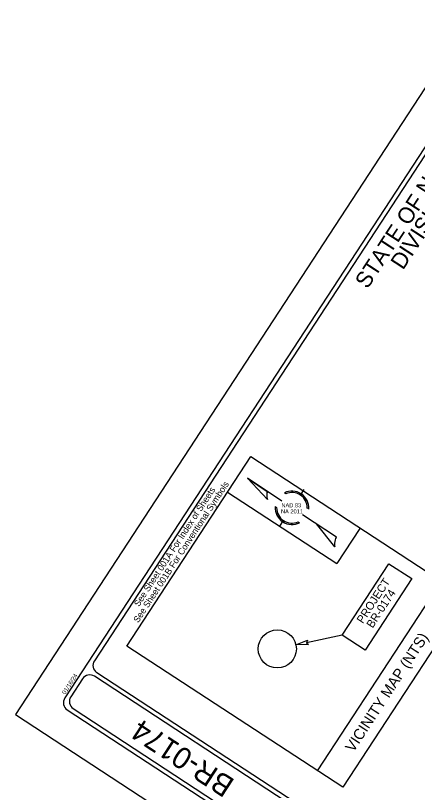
# Model space of a CAD drawing. Extents: x 1190029 to 2382315, y 163128 to 334830.
# Drawn here: x 2378613 to 2379548, y 331527 to 333329 of the extents above; entities that cross this region are included whole.
import ezdxf

# ---------------------------------------------------------------- set-up
doc = ezdxf.new("R2010")
doc.units = 0
for name, color, linetype in [('Exist Property Corner CELL', 7, 'Continuous'), ('Exist Utilities Telephone UG FO SUE LOS B Text', 7, 'Continuous'), ('P_NCDOT_Vertical_Profile_Strip_Grade', 7, 'Continuous'), ('Scratch_Level_4', 7, 'Continuous'), ('Sheet Block Title CELL', 7, 'Continuous'), ('Sheet PE Seal CELL', 7, 'Continuous'), ('z - Construction', 7, 'Continuous')]:
    doc.layers.add(name, color=color, linetype=linetype)

msp = doc.modelspace()

# ---------------------------------------------------------------- linework, layer by layer
at = {"layer": 'Exist Property Corner CELL'}
msp.add_line((2379261.2, 332185.5), (2379261.2, 332185.5), dxfattribs=at)
msp.add_line((2379261.2, 332185.5), (2379261.2, 332185.5), dxfattribs=at)
msp.add_line((2379261.2, 332185.5), (2379261.2, 332185.5), dxfattribs=at)
msp.add_line((2379261.2, 332185.5), (2379261.2, 332185.5), dxfattribs=at)
msp.add_line((2379261.2, 332185.5), (2379261.2, 332185.5), dxfattribs=at)
msp.add_line((2379261.2, 332185.5), (2379261.2, 332185.5), dxfattribs=at)
msp.add_line((2379261.2, 332185.5), (2379261.2, 332185.5), dxfattribs=at)
msp.add_line((2379261.2, 332185.5), (2379261.2, 332185.5), dxfattribs=at)
msp.add_line((2379261.2, 332185.5), (2379261.2, 332185.5), dxfattribs=at)
msp.add_line((2379261.2, 332185.5), (2379261.2, 332185.5), dxfattribs=at)
msp.add_line((2379261.2, 332185.5), (2379261.2, 332185.5), dxfattribs=at)
for start_param, end_param in [(0.216388, 2.908219), (0.201328, 3.141593)]:
    msp.add_ellipse((2379261.2, 332185.5), major_axis=(0.000000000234, 0.000000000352), ratio=0.461098, start_param=start_param, end_param=end_param, dxfattribs=at)
at = {"layer": 'Exist Utilities Telephone UG FO SUE LOS B Text'}
for p, q in [((2380483.9, 334428.7), (2378727.4, 331741.9)), ((2380486.9, 334414.8), (2378796.1, 331828.5)), ((2378871.7, 331862.7), (2379159.9, 332303.6)), ((2379159.9, 332303.6), (2379662.2, 331975.2)), ((2379105.8, 332220.7), (2379360.2, 332054.4)), ((2379413.9, 332136.4), (2379360.2, 332054.4)), ((2379602.6, 332013.1), (2379314.3, 331572.2)), ((2379662.2, 331975.2), (2379374, 331534.3)), ((2379374, 331534.3), (2378871.7, 331862.7)), ((2380462, 330703.5), (2378796.4, 331792.4)), ((2380157.8, 330914.3), (2378801.9, 331800.8)), ((2378747.1, 331717.1), (2380412.8, 330628.2)), ((2378733.2, 331714.3), (2380415.6, 330614.4))]:
    msp.add_line(p, q, dxfattribs=at)
msp.add_lwpolyline([(2378768.6, 331786.7), (2378741.3, 331744.8)], dxfattribs=at)
for centre, start, end in [((2378812.8, 331817.5), 146.8248, 236.8248), ((2378785.4, 331775.7), 56.8248, 146.8248), ((2378744.1, 331731), 146.8248, 236.8248), ((2378758, 331733.9), 146.8248, 236.8248)]:
    msp.add_arc(centre, 20, start, end, dxfattribs=at)
at = {"layer": 'P_NCDOT_Vertical_Profile_Strip_Grade'}
for p, q in [((2379199, 332203.8), (2379152.1, 332252.9)), ((2379232.5, 332199.7), (2379152.2, 332252.9)), ((2379152.2, 332252.9), (2379200.5, 332220.9)), ((2379200.5, 332220.9), (2379199.1, 332221.8)), ((2379199.1, 332221.8), (2379199.1, 332221.8)), ((2379275.5, 332214), (2379284.2, 332227)), ((2379241.4, 332216.9), (2379238.1, 332219)), ((2379275.5, 332214), (2379277.3, 332216.7)), ((2379277.3, 332216.7), (2379275.5, 332214)), ((2379216.8, 332187.1), (2379216.9, 332187)), ((2379216.9, 332187), (2379220.1, 332184.9)), ((2379359.4, 332115.6), (2379280.2, 332168)), ((2379294.7, 332181.5), (2379291.4, 332183.7)), ((2379294.7, 332181.5), (2379294.7, 332181.5)), ((2379227.4, 332141.4), (2379236.1, 332154.5)), ((2379236.1, 332154.5), (2379234.2, 332151.7)), ((2379234.2, 332151.7), (2379236.1, 332154.5)), ((2379270.3, 332151.7), (2379273.5, 332149.5)), ((2379311.8, 332147.1), (2379355.1, 332093.8)), ((2379359.4, 332115.6), (2379311.8, 332147.1))]:
    msp.add_line(p, q, dxfattribs=at)
for radius, start, end in [(39, 355.9746, 116.9338), (39, 56.4542, 116.9338), (35.7, 359.0548, 113.8536), (35.7, 56.4542, 113.8536), (39, 175.8884, 297.0201), (35.7, 178.9574, 293.9511), (39, 236.4542, 297.0201), (35.7, 236.4542, 293.9511)]:
    msp.add_arc((2379255.8, 332184.2), radius, start, end, dxfattribs=at)
for centre, major_axis, ratio, start_param, end_param in [((2379199.6, 332212.3), (-0.65, 9.54), 0.261723, 6.225794, 8.917625), ((2379255.8, 332184.2), (-29.8, 19.7), 0.998737, 3.71058, 4.712389), ((2379255.8, 332184.2), (-32.5, 21.6), 0.998737, 3.657116, 4.712389), ((2379255.8, 332184.2), (-32.5, 21.6), 0.998737, 0.514018, 1.570796), ((2379255.8, 332184.2), (-29.8, 19.7), 0.998737, 0.567287, 1.570796), ((2379357.5, 332104.5), (1.8, 11.1), 0.225493, 6.280036, 9.220301)]:
    msp.add_ellipse(centre, major_axis=major_axis, ratio=ratio, start_param=start_param, end_param=end_param, dxfattribs=at)
at = {"layer": 'Scratch_Level_4'}
msp.add_line((2379372.6, 331887.9), (2379289.8, 331870.4), dxfattribs=at)
msp.add_circle((2379221.7, 331856.1), 44.3, dxfattribs=at)
at = {"layer": 'Sheet Block Title CELL'}
msp.add_lwpolyline([(2379294.2, 331866.4), (2379265, 331865.2), (2379292.2, 331876.2), (2379289.7, 331870.5)], close=True, dxfattribs=at)
at = {"layer": 'Sheet PE Seal CELL'}
msp.add_lwpolyline([(2379372.6, 331887.9), (2379481.4, 332054.3), (2379534.5, 332019.6), (2379425.8, 331853.2)], close=True, dxfattribs=at)
at = {"layer": 'z - Construction'}
for p, q in [((2380473.1, 334549.3), (2378612.6, 331703.5)), ((2378612.6, 331703.5), (2380454, 330499.6))]:
    msp.add_line(p, q, dxfattribs=at)

# ---------------------------------------------------------------- texts
at = {"layer": 'Exist Utilities Telephone UG FO SUE LOS B Text'}
for s, height, rotation, p in [('STATE OF NORTH CAROLINA', 37.5, 56.8248, (2379431.4, 332691.4)), ('DIVISION OF HIGHWAYS', 37.5, 56.8248, (2379514.1, 332735.6)), ('See Sheet 001B For Conventional Symbols', 15, 56.8248, (2378898.3, 331915.6)), ('See Sheet 001A For Index of Sheets', 15, 56.8248, (2378899.6, 331953)), ('VICINITY MAP (NTS)', 25, 56.8248, (2379398.8, 331614.2)), ('01/16/24', 10, 56.8248, (2378728.3, 331749.2)), ('BR-0174 ', 50, 146.8248, (2379125.3, 331550.2))]:
    msp.add_text(s, height=height, rotation=rotation, dxfattribs=at).set_placement(p)
at = {"layer": 'P_NCDOT_Vertical_Profile_Strip_Grade'}
for s, p in [('NAD 83', (2379231.3, 332185.4)), ('NA 2011', (2379230.3, 332171.2))]:
    msp.add_text(s, height=9.51, dxfattribs=at).set_placement(p)
at = {"layer": 'Sheet PE Seal CELL'}
for s, p in [('PROJECT', (2379420.7, 331913.6)), ('BR-0174', (2379443.4, 331903))]:
    msp.add_text(s, height=18.93, rotation=56.8377, dxfattribs=at).set_placement(p)

doc.saveas('drawing.dxf')
